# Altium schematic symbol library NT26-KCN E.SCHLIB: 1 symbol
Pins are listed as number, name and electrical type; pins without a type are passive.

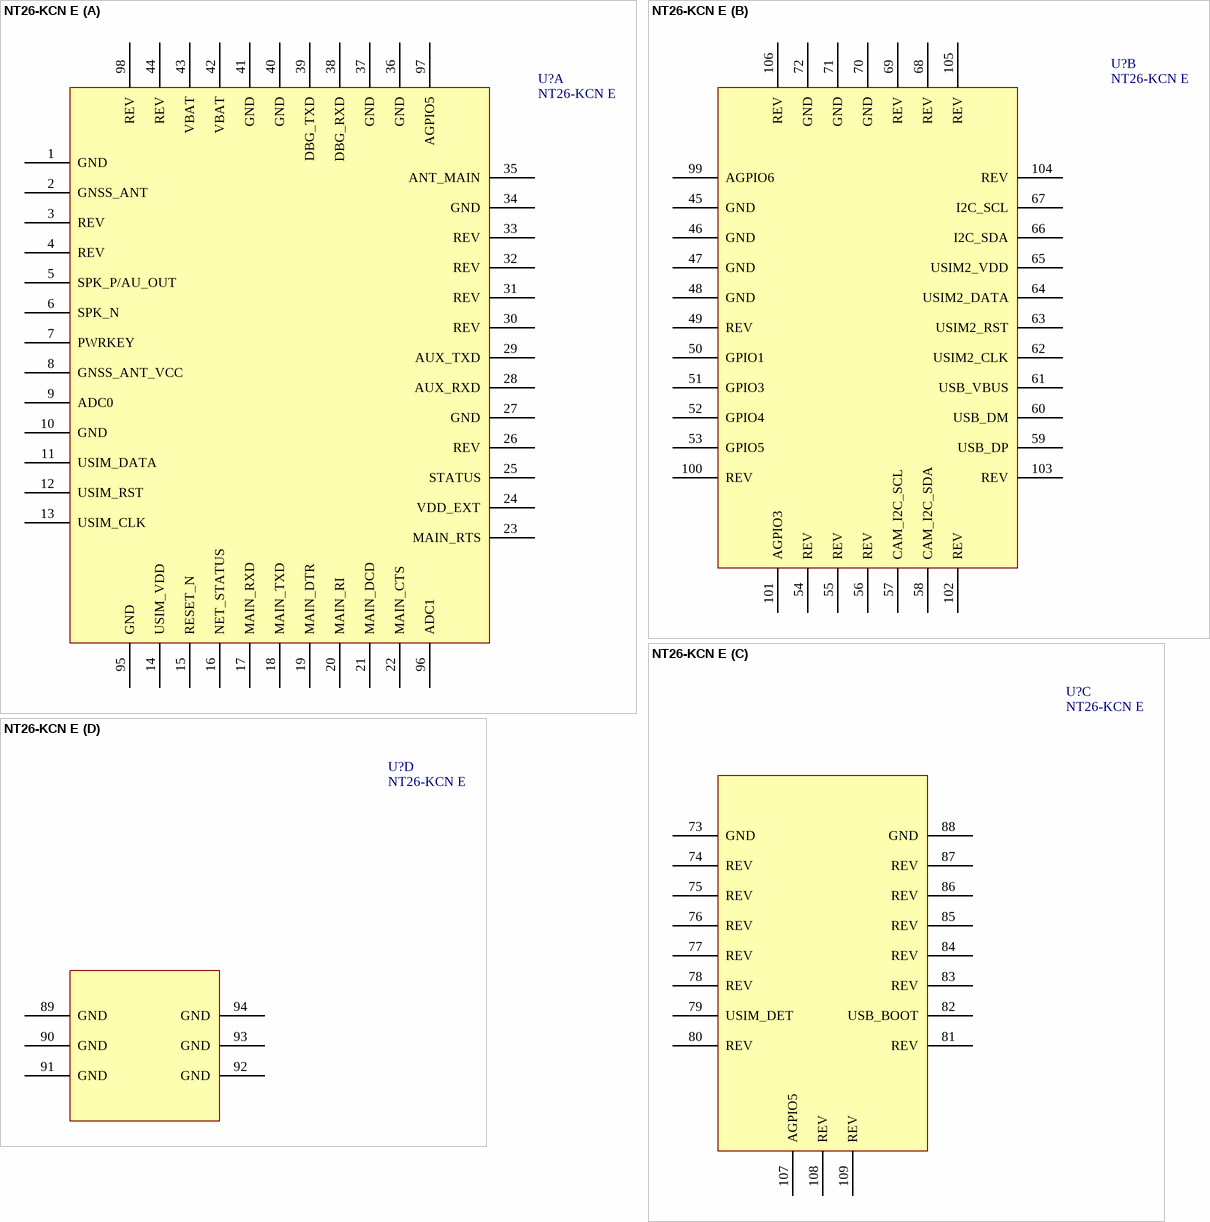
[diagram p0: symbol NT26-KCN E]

## NT26-KCN E
designator U?
footprint NT26-KCN E (Footprint not found)
part A pins: 1 GND, 2 GNSS_ANT, 3 REV, 4 REV, 5 SPK_P/AU_OUT, 6 SPK_N, 7 PWRKEY, 8 GNSS_ANT_VCC, 9 ADC0, 10 GND, 11 USIM_DATA, 12 USIM_RST, 13 USIM_CLK, 14 USIM_VDD, 15 RESET_N, 16 NET_STATUS, 17 MAIN_RXD, 18 MAIN_TXD, 19 MAIN_DTR, 20 MAIN_RI, 21 MAIN_DCD, 22 MAIN_CTS, 23 MAIN_RTS, 24 VDD_EXT, 25 STATUS, 26 REV, 27 GND, 28 AUX_RXD, 29 AUX_TXD, 30 REV, 31 REV, 32 REV, 33 REV, 34 GND, 35 ANT_MAIN, 36 GND, 37 GND, 38 DBG_RXD, 39 DBG_TXD, 40 GND, 41 GND, 42 VBAT, 43 VBAT, 44 REV, 95 GND, 96 ADC1, 97 AGPIO5, 98 REV
part B pins: 45 GND, 46 GND, 47 GND, 48 GND, 49 REV, 50 GPIO1, 51 GPIO3, 52 GPIO4, 53 GPIO5, 54 REV, 55 REV, 56 REV, 57 CAM_I2C_SCL, 58 CAM_I2C_SDA, 59 USB_DP, 60 USB_DM, 61 USB_VBUS, 62 USIM2_CLK, 63 USIM2_RST, 64 USIM2_DATA, 65 USIM2_VDD, 66 I2C_SDA, 67 I2C_SCL, 68 REV, 69 REV, 70 GND, 71 GND, 72 GND, 99 AGPIO6, 100 REV, 101 AGPIO3, 102 REV, 103 REV, 104 REV, 105 REV, 106 REV
part C pins: 73 GND, 74 REV, 75 REV, 76 REV, 77 REV, 78 REV, 79 USIM_DET, 80 REV, 81 REV, 82 USB_BOOT, 83 REV, 84 REV, 85 REV, 86 REV, 87 REV, 88 GND, 107 AGPIO5, 108 REV, 109 REV
part D pins: 89 GND, 90 GND, 91 GND, 92 GND, 93 GND, 94 GND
